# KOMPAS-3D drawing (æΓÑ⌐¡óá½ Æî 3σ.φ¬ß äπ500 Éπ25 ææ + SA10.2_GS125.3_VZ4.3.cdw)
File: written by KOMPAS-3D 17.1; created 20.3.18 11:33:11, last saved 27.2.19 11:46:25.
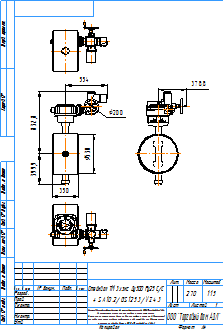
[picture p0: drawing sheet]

Sheet 1: A4, portrait

Title block, sheet 1: name: Стейнвал ТМ 3х.экс Ду500 Ру25 С/С / + SA10.2/GS125.3/VZ4.3; mass: 270; sheets: 1; sheet format: A4; stored path: \\adlc.lan\data\АДЛ_ПКД\3D-модели\ADL production\Дисковые поворотные затворы СТЕЙНВАЛ\Трехэксцентриковый\Стейнвал c-c\С эл.приводом\KOMPAS 2D\Стейнвал ТМ 3х.экс Ду500 Ру25 СС + SA10.2_GS125.3_VZ4.3.cdw

Views: Вид 1, Проекционный вид 3, Проекционный вид 4
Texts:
  kka
  adl
  Рама для чертежей
  Лит-Масса-Масштаб
  Материал-Предприятие
  Масштаб
  Изм.
  Лист
  № докум.
  Подп.
  Дата
  Лит.
  Разраб.
  Пров.
  Т.контр.
  Листов
  Внимание! Данный продукт является объектом авторского права ООО «Торговый Дом АДЛ».
  Запрещается изменение, копирование, распространение
  (в том числе путем копирования на другие сайты и ресурсы в Интернете)
  или любое иное использование информации и объектов без предварительного
  согласия правообладателя (ООО «Торговый Дом АДЛ»).
  Н.контр.
  Утв.
  ООО "Торговый дом АДЛ"
  Изменение
  Номер документа
  Подпись
  Обозначение документа
  Наименование изделия
  Масса изделия по ГОСТ 2.109-73
  Порядковый номер листа
  Общее количество листов в документе
  Характер работы, выполненной лицом, подписавшим документ
  Наименование или индекс предприятия, выпускающего документ
  Инв. № подл.
  Подп. и дата
  Взам. инв. №
  Инв. № дубл.
  Инвентарный номер подлинника по ГОСТ 2.501-68
  Подпись принявшего подлинник в отдел технической документации
  Инвентарный номер подлинника, взамен которого выпущен данный подлинник
  Инвентарный номер дубликата по ГОСТ 2.502-68
  Подпись принявшего дубликат в отдел технической документации
  Справ. №
  Перв. примен.
  Обозначение документа, взамен или на основании которого выпущен данный документ
  Обозначение документа, в котором впервые записан данный документ
  Подпись лица, копировавшего чертеж
  Обозначение формата листа
  !Рама для чертежа
Dimensions and other numbers on the sheet: 200; 350; 399,9; 832,8; 530; 554; 1:15; 1; 270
